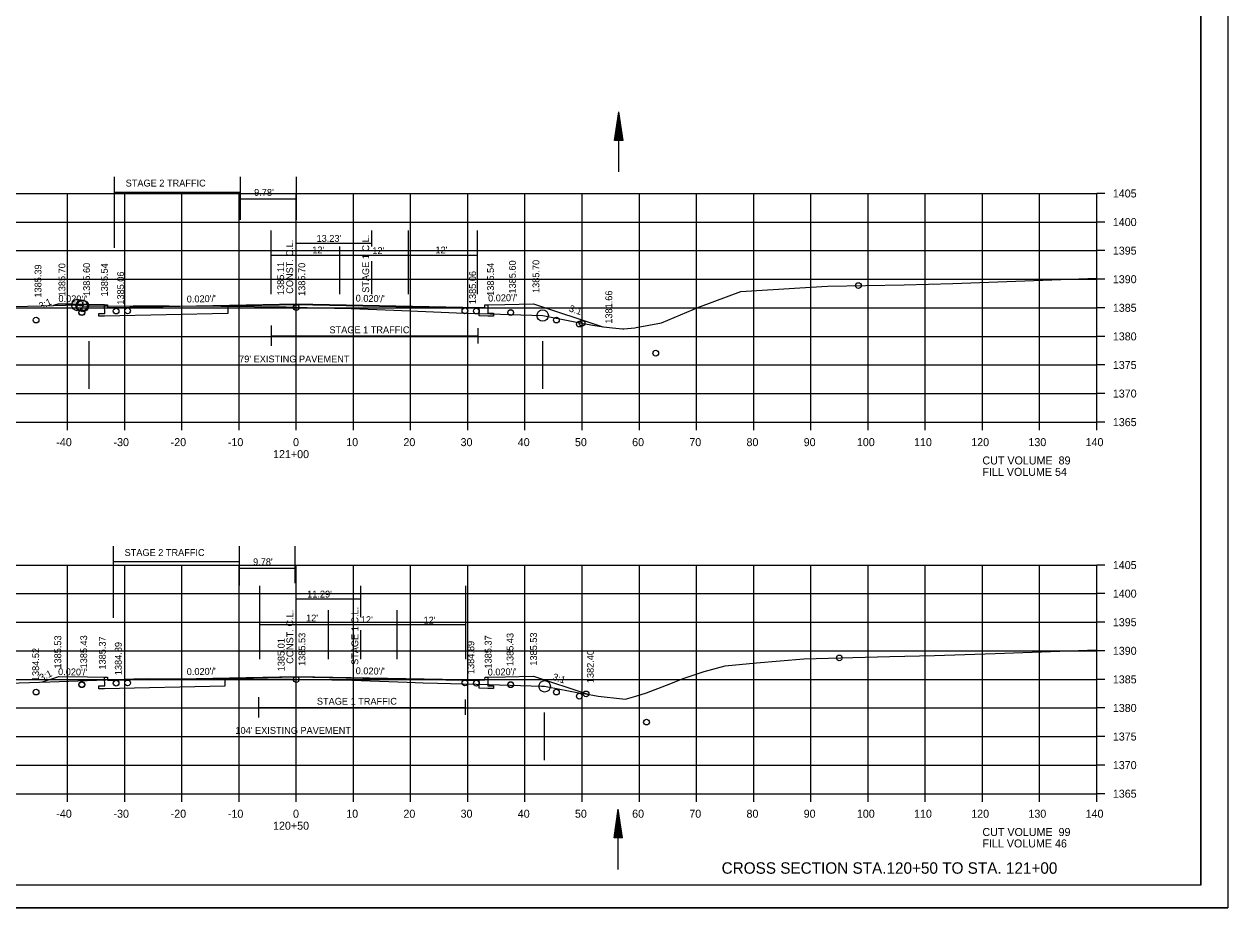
# Model space of a CAD drawing. Extents: x 1374311 to 1383814, y 384102 to 406278.
# Drawn here: x 1381581.1 to 1381791.6, y 385391.3 to 385545.9 of the extents above; entities that cross this region are included whole.
import ezdxf

# ---------------------------------------------------------------- set-up
doc = ezdxf.new("R2010")
doc.units = 0
for name, color, linetype in [('R_Axis', 7, 'Continuous'), ('R_Axis Annot', 7, 'Continuous'), ('R_Border', 7, 'Continuous'), ('R_Draft', 7, 'Continuous'), ('R_Exist Surface', 7, 'Continuous'), ('R_Fin Surface', 7, 'Continuous'), ('R_Grid', 7, 'Continuous'), ('R_No Plot', 7, 'Continuous'), ('R_Water', 7, 'Continuous'), ('R_Xsect Elev', 7, 'Continuous'), ('R_Xsect Slope', 7, 'Continuous')]:
    doc.layers.add(name, color=color, linetype=linetype)

msp = doc.modelspace()

# ---------------------------------------------------------------- linework, layer by layer
at = {"layer": 'R_Axis'}
for p, q in [((1381768.66, 385476.27), (1381768.66, 385516.27)), ((1381770.06, 385516.27), (1381768.66, 385516.27)), ((1381770.06, 385511.27), (1381768.66, 385511.27)), ((1381770.06, 385506.27), (1381768.66, 385506.27)), ((1381770.06, 385501.27), (1381768.66, 385501.27)), ((1381770.06, 385496.27), (1381768.66, 385496.27)), ((1381770.06, 385491.27), (1381768.66, 385491.27)), ((1381770.06, 385486.27), (1381768.66, 385486.27)), ((1381770.06, 385481.27), (1381768.66, 385481.27)), ((1381488.66, 385476.27), (1381768.66, 385476.27)), ((1381588.66, 385474.87), (1381588.66, 385476.27)), ((1381598.66, 385474.87), (1381598.66, 385476.27)), ((1381608.66, 385474.87), (1381608.66, 385476.27)), ((1381618.66, 385474.87), (1381618.66, 385476.27)), ((1381628.66, 385474.87), (1381628.66, 385476.27)), ((1381638.66, 385474.87), (1381638.66, 385476.27)), ((1381648.66, 385474.87), (1381648.66, 385476.27)), ((1381658.66, 385474.87), (1381658.66, 385476.27)), ((1381668.66, 385474.87), (1381668.66, 385476.27)), ((1381678.66, 385474.87), (1381678.66, 385476.27)), ((1381688.66, 385474.87), (1381688.66, 385476.27)), ((1381698.66, 385474.87), (1381698.66, 385476.27)), ((1381708.66, 385474.87), (1381708.66, 385476.27)), ((1381718.66, 385474.87), (1381718.66, 385476.27)), ((1381728.66, 385474.87), (1381728.66, 385476.27)), ((1381738.66, 385474.87), (1381738.66, 385476.27)), ((1381748.66, 385474.87), (1381748.66, 385476.27)), ((1381758.66, 385474.87), (1381758.66, 385476.27)), ((1381768.66, 385474.87), (1381768.66, 385476.27)), ((1381770.06, 385476.27), (1381768.66, 385476.27)), ((1381768.66, 385411.27), (1381768.66, 385451.27)), ((1381770.06, 385451.27), (1381768.66, 385451.27)), ((1381770.06, 385446.27), (1381768.66, 385446.27)), ((1381770.06, 385441.27), (1381768.66, 385441.27)), ((1381770.06, 385436.27), (1381768.66, 385436.27)), ((1381770.06, 385431.27), (1381768.66, 385431.27)), ((1381770.06, 385426.27), (1381768.66, 385426.27)), ((1381770.06, 385421.27), (1381768.66, 385421.27)), ((1381770.06, 385416.27), (1381768.66, 385416.27)), ((1381488.66, 385411.27), (1381768.66, 385411.27)), ((1381588.66, 385409.87), (1381588.66, 385411.27)), ((1381598.66, 385409.87), (1381598.66, 385411.27)), ((1381608.66, 385409.87), (1381608.66, 385411.27)), ((1381618.66, 385409.87), (1381618.66, 385411.27)), ((1381628.66, 385409.87), (1381628.66, 385411.27)), ((1381638.66, 385409.87), (1381638.66, 385411.27)), ((1381648.66, 385409.87), (1381648.66, 385411.27)), ((1381658.66, 385409.87), (1381658.66, 385411.27)), ((1381668.66, 385409.87), (1381668.66, 385411.27)), ((1381678.66, 385409.87), (1381678.66, 385411.27)), ((1381688.66, 385409.87), (1381688.66, 385411.27)), ((1381698.66, 385409.87), (1381698.66, 385411.27)), ((1381708.66, 385409.87), (1381708.66, 385411.27)), ((1381718.66, 385409.87), (1381718.66, 385411.27)), ((1381728.66, 385409.87), (1381728.66, 385411.27)), ((1381738.66, 385409.87), (1381738.66, 385411.27)), ((1381748.66, 385409.87), (1381748.66, 385411.27)), ((1381758.66, 385409.87), (1381758.66, 385411.27)), ((1381768.66, 385409.87), (1381768.66, 385411.27)), ((1381770.06, 385411.27), (1381768.66, 385411.27))]:
    msp.add_line(p, q, dxfattribs=at)
at = {"layer": 'R_Border'}
for q in [(1381786.84, 385600.73), (1381470.66, 385395.27)]:
    msp.add_line((1381786.84, 385395.27), q, dxfattribs=at)
at = {"layer": 'R_Draft'}
for p, q in [((1381684.33, 385525.56), (1381685.08, 385530.56)), ((1381684.46, 385525.56), (1381685.08, 385529.72)), ((1381684.59, 385525.56), (1381685.08, 385528.86)), ((1381685.83, 385525.56), (1381685.08, 385530.56)), ((1381685.71, 385525.56), (1381685.08, 385529.72)), ((1381685.58, 385525.56), (1381685.08, 385528.86)), ((1381684.71, 385525.56), (1381685.08, 385528.03)), ((1381684.84, 385525.56), (1381685.08, 385527.18)), ((1381685.46, 385525.56), (1381685.08, 385528.03)), ((1381685.33, 385525.56), (1381685.08, 385527.18)), ((1381685.83, 385525.56), (1381684.33, 385525.56)), ((1381684.97, 385525.56), (1381685.08, 385526.35)), ((1381685.2, 385525.56), (1381685.08, 385526.35)), ((1381684.23, 385403.55), (1381684.98, 385408.55)), ((1381684.36, 385403.55), (1381684.98, 385407.72)), ((1381684.49, 385403.55), (1381684.98, 385406.86)), ((1381685.73, 385403.55), (1381684.98, 385408.55)), ((1381685.61, 385403.55), (1381684.98, 385407.72)), ((1381685.48, 385403.55), (1381684.98, 385406.86)), ((1381684.61, 385403.55), (1381684.98, 385406.02)), ((1381684.74, 385403.55), (1381684.98, 385405.18)), ((1381685.36, 385403.55), (1381684.98, 385406.02)), ((1381685.23, 385403.55), (1381684.98, 385405.18)), ((1381685.73, 385403.55), (1381684.23, 385403.55)), ((1381684.87, 385403.55), (1381684.98, 385404.34)), ((1381685.1, 385403.55), (1381684.98, 385404.34))]:
    msp.add_line(p, q, dxfattribs=at)
at = {"layer": 'R_Exist Surface'}
for points in [[(1381566.63, 385496.21), (1381584.14, 385496.61), (1381590.37, 385496.77), (1381590.75, 385496.7), (1381591.14, 385496.66), (1381591.22, 385496.59), (1381591.35, 385496.58), (1381600.13, 385496.61), (1381602.79, 385496.61), (1381606.43, 385496.6), (1381615.47, 385496.58), (1381621.3, 385496.51), (1381626.89, 385496.43), (1381632.35, 385496.29), (1381638.29, 385496.15), (1381645.72, 385495.87), (1381651.3, 385495.65), (1381656.7, 385495.42), (1381662.59, 385495.19), (1381667.95, 385495.02), (1381671.76, 385494.91), (1381676.77, 385493.95), (1381678.18, 385493.66), (1381680.5, 385493.26), (1381682.39, 385492.92), (1381683.95, 385492.76), (1381685.73, 385492.59), (1381685.97, 385492.62), (1381687.85, 385492.76), (1381688.1, 385492.8), (1381692.56, 385493.62), (1381698.05, 385495.99), (1381698.99, 385496.39), (1381699.34, 385496.51), (1381706.38, 385499.12), (1381716.72, 385499.78), (1381721.58, 385500.07), (1381734.99, 385500.28), (1381743.49, 385500.53), (1381768.66, 385501.48)], [(1381573.05, 385430.41), (1381585.57, 385430.84), (1381600.25, 385431.34), (1381600.44, 385431.36), (1381602.76, 385431.4), (1381614.38, 385431.38), (1381614.97, 385431.38), (1381615.52, 385431.37), (1381626.91, 385431.31), (1381627.83, 385431.29), (1381638.38, 385431.14), (1381648.06, 385430.79), (1381650.88, 385430.69), (1381653.36, 385430.61), (1381662.38, 385430.36), (1381671.55, 385430.07), (1381672.1, 385430.06), (1381672.63, 385429.95), (1381678.06, 385428.93), (1381678.93, 385428.8), (1381681.43, 385428.36), (1381685.74, 385427.85), (1381686.31, 385427.78), (1381686.4, 385427.84), (1381688.06, 385428.36), (1381689.94, 385428.91), (1381693.38, 385430.25), (1381696.52, 385431.49), (1381699.98, 385432.64), (1381703.67, 385433.63), (1381709.14, 385434.16), (1381717.45, 385434.86), (1381732.46, 385435.27), (1381740.27, 385435.44), (1381750.89, 385435.82), (1381768.66, 385436.44)]]:
    msp.add_lwpolyline(points, dxfattribs=at)
at = {"layer": 'R_Fin Surface'}
for points in [[(1381586.23, 385496.67), (1381587.15, 385496.97), (1381592.15, 385496.87), (1381595.15, 385496.81), (1381595.65, 385496.81), (1381595.66, 385496.31), (1381596.66, 385496.33), (1381628.66, 385496.97), (1381628.66, 385496.97)], [(1381628.66, 385496.8), (1381628.66, 385496.8), (1381616.68, 385496.56), (1381616.68, 385495.25), (1381595.15, 385494.82), (1381594.15, 385494.8), (1381594.16, 385495.3), (1381595.16, 385495.3), (1381595.14, 385496.81)], [(1381628.66, 385496.97), (1381660.65, 385496.33)], [(1381660.65, 385496.16), (1381628.66, 385496.8)], [(1381660.65, 385496.33), (1381661.64, 385496.31), (1381661.65, 385496.81), (1381662.15, 385496.81), (1381665.15, 385496.87), (1381670.15, 385496.97), (1381682.26, 385492.94)], [(1381662.16, 385496.81), (1381662.17, 385495.31), (1381663.17, 385495.31), (1381663.16, 385494.81), (1381662.16, 385494.83), (1381660.65, 385494.85), (1381660.65, 385496.16)], [(1381584.12, 385430.79), (1381587.15, 385431.8), (1381592.15, 385431.7), (1381595.15, 385431.64), (1381595.65, 385431.64), (1381595.66, 385431.14), (1381596.66, 385431.16), (1381628.66, 385431.8), (1381660.66, 385431.19), (1381661.66, 385431.17), (1381661.67, 385431.67), (1381662.17, 385431.67), (1381665.17, 385431.73), (1381670.17, 385431.83), (1381679.66, 385428.67)], [(1381662.16, 385431.67), (1381662.18, 385430.16), (1381663.18, 385430.16), (1381663.17, 385429.66), (1381662.17, 385429.68), (1381660.66, 385429.71), (1381660.66, 385431.02), (1381628.66, 385431.63), (1381616.17, 385431.38), (1381616.17, 385430.06), (1381595.15, 385429.64), (1381594.15, 385429.62), (1381594.16, 385430.12), (1381595.16, 385430.13), (1381595.14, 385431.64)]]:
    msp.add_lwpolyline(points, dxfattribs=at)
at = {"layer": 'R_Grid'}
for p, q in [((1381488.66, 385516.27), (1381768.66, 385516.27)), ((1381588.66, 385476.27), (1381588.66, 385516.27)), ((1381598.66, 385476.27), (1381598.66, 385516.27)), ((1381608.66, 385476.27), (1381608.66, 385516.27)), ((1381618.66, 385476.27), (1381618.66, 385516.27)), ((1381628.66, 385476.27), (1381628.66, 385516.27)), ((1381638.66, 385476.27), (1381638.66, 385516.27)), ((1381648.66, 385476.27), (1381648.66, 385516.27)), ((1381658.66, 385476.27), (1381658.66, 385516.27)), ((1381668.66, 385476.27), (1381668.66, 385516.27)), ((1381678.66, 385476.27), (1381678.66, 385516.27)), ((1381688.66, 385476.27), (1381688.66, 385516.27)), ((1381698.66, 385476.27), (1381698.66, 385516.27)), ((1381708.66, 385476.27), (1381708.66, 385516.27)), ((1381718.66, 385476.27), (1381718.66, 385516.27)), ((1381728.66, 385476.27), (1381728.66, 385516.27)), ((1381738.66, 385476.27), (1381738.66, 385516.27)), ((1381748.66, 385476.27), (1381748.66, 385516.27)), ((1381758.66, 385476.27), (1381758.66, 385516.27)), ((1381768.66, 385476.27), (1381768.66, 385516.27)), ((1381488.66, 385511.27), (1381768.66, 385511.27)), ((1381488.66, 385506.27), (1381768.66, 385506.27)), ((1381488.66, 385501.27), (1381768.66, 385501.27)), ((1381488.66, 385496.27), (1381768.66, 385496.27)), ((1381488.66, 385491.27), (1381768.66, 385491.27)), ((1381488.66, 385486.27), (1381768.66, 385486.27)), ((1381488.66, 385481.27), (1381768.66, 385481.27)), ((1381488.66, 385476.27), (1381768.66, 385476.27)), ((1381488.66, 385451.27), (1381768.66, 385451.27)), ((1381588.66, 385411.27), (1381588.66, 385451.27)), ((1381598.66, 385411.27), (1381598.66, 385451.27)), ((1381608.66, 385411.27), (1381608.66, 385451.27)), ((1381618.66, 385411.27), (1381618.66, 385451.27)), ((1381628.66, 385411.27), (1381628.66, 385451.27)), ((1381638.66, 385411.27), (1381638.66, 385451.27)), ((1381648.66, 385411.27), (1381648.66, 385451.27)), ((1381658.66, 385411.27), (1381658.66, 385451.27)), ((1381668.66, 385411.27), (1381668.66, 385451.27)), ((1381678.66, 385411.27), (1381678.66, 385451.27)), ((1381688.66, 385411.27), (1381688.66, 385451.27)), ((1381698.66, 385411.27), (1381698.66, 385451.27)), ((1381708.66, 385411.27), (1381708.66, 385451.27)), ((1381718.66, 385411.27), (1381718.66, 385451.27)), ((1381728.66, 385411.27), (1381728.66, 385451.27)), ((1381738.66, 385411.27), (1381738.66, 385451.27)), ((1381748.66, 385411.27), (1381748.66, 385451.27)), ((1381758.66, 385411.27), (1381758.66, 385451.27)), ((1381768.66, 385411.27), (1381768.66, 385451.27)), ((1381488.66, 385446.27), (1381768.66, 385446.27)), ((1381488.66, 385441.27), (1381768.66, 385441.27)), ((1381488.66, 385436.27), (1381768.66, 385436.27)), ((1381488.66, 385431.27), (1381768.66, 385431.27)), ((1381488.66, 385426.27), (1381768.66, 385426.27)), ((1381488.66, 385421.27), (1381768.66, 385421.27)), ((1381488.66, 385416.27), (1381768.66, 385416.27)), ((1381488.66, 385411.27), (1381768.66, 385411.27))]:
    msp.add_line(p, q, dxfattribs=at)
at = {"layer": 'R_No Plot'}
msp.add_line((1381458.26, 385391.29), (1381791.59, 385391.29), dxfattribs=at)
for points in [[(1381458.25, 385604.63), (1381791.59, 385604.63), (1381791.59, 385391.29), (1381458.25, 385391.29)], [(1381704.58, 385600.73), (1381704.58, 385590.85), (1381740.31, 385590.85), (1381740.31, 385587.93), (1381763.51, 385587.93), (1381763.51, 385564.72), (1381786.84, 385564.72), (1381786.84, 385395.27), (1381470.66, 385395.27), (1381470.66, 385600.73)], [(1381586.23, 385496.67), (1381590.37, 385496.77), (1381590.75, 385496.7), (1381591.14, 385496.66), (1381591.22, 385496.59), (1381591.35, 385496.58), (1381595.15, 385496.59), (1381595.15, 385496.81), (1381592.15, 385496.87), (1381587.15, 385496.97)]]:
    msp.add_lwpolyline(points, close=True, dxfattribs=at)
for centre, radius in [((1381726.97, 385500.15), 0.5), ((1381590.37, 385496.77), 1), ((1381591.14, 385496.66), 1), ((1381591.35, 385496.58), 1), ((1381591.16, 385495.46), 0.5), ((1381591.16, 385495.42), 0.5), ((1381597.16, 385495.7), 0.5), ((1381599.16, 385495.74), 0.5), ((1381599.16, 385495.74), 0.5), ((1381628.66, 385496.33), 0.5), ((1381628.66, 385496.33), 0.5), ((1381658.16, 385495.74), 0.5), ((1381658.16, 385495.74), 0.5), ((1381660.16, 385495.7), 0.5), ((1381666.16, 385495.46), 0.5), ((1381666.16, 385495.42), 0.5), ((1381671.76, 385494.91), 1), ((1381583.16, 385494.13), 0.5), ((1381674.16, 385494.13), 0.5), ((1381678.16, 385493.42), 0.5), ((1381678.64, 385493.58), 0.5), ((1381691.53, 385488.34), 0.5), ((1381723.63, 385435.03), 0.5), ((1381591.16, 385430.37), 0.5), ((1381591.16, 385430.33), 0.5), ((1381597.16, 385430.61), 0.5), ((1381599.16, 385430.65), 0.5), ((1381599.16, 385430.65), 0.5), ((1381628.66, 385431.24), 0.5), ((1381628.66, 385431.24), 0.5), ((1381658.16, 385430.65), 0.5), ((1381658.16, 385430.65), 0.5), ((1381660.16, 385430.61), 0.5), ((1381666.16, 385430.37), 0.5), ((1381666.16, 385430.33), 0.5), ((1381672.1, 385430.06), 1), ((1381583.16, 385429.04), 0.5), ((1381674.16, 385429.04), 0.5), ((1381678.16, 385428.33), 0.5), ((1381679.34, 385428.73), 0.5), ((1381689.91, 385423.79), 0.5)]:
    msp.add_circle(centre, radius, dxfattribs=at)
at = {"layer": 'R_Water'}
for p, q in [((1381685.08, 385520.05), (1381685.08, 385530.56)), ((1381596.9, 385506.74), (1381596.9, 385519.18)), ((1381618.9, 385511.66), (1381618.9, 385519.18)), ((1381628.68, 385511.66), (1381628.68, 385519.18)), ((1381596.9, 385516.52), (1381618.9, 385516.52)), ((1381618.9, 385515.33), (1381628.68, 385515.33)), ((1381624.29, 385498.67), (1381624.29, 385509.81)), ((1381628.66, 385506.97), (1381628.66, 385509.81)), ((1381641.89, 385506.97), (1381641.89, 385509.81)), ((1381648.31, 385498.67), (1381648.31, 385509.81)), ((1381660.36, 385498.67), (1381660.36, 385509.81)), ((1381628.66, 385507.58), (1381641.89, 385507.58)), ((1381636.29, 385498.67), (1381636.29, 385506.97)), ((1381624.29, 385505.5), (1381660.36, 385505.5)), ((1381628.66, 385498.67), (1381628.66, 385504.34)), ((1381641.89, 385498.67), (1381641.89, 385504.42)), ((1381628.66, 385496.97), (1381660.65, 385496.33)), ((1381624.34, 385489.61), (1381624.34, 385493.16)), ((1381624.33, 385491.37), (1381660.47, 385491.37)), ((1381660.47, 385490.02), (1381660.47, 385492.71)), ((1381592.43, 385482.12), (1381592.43, 385490.45)), ((1381671.76, 385482.12), (1381671.76, 385490.45)), ((1381592.43, 385486.29), (1381671.76, 385486.29)), ((1381596.71, 385442.05), (1381596.71, 385454.55)), ((1381618.71, 385447.72), (1381618.71, 385454.55)), ((1381628.49, 385448.08), (1381628.49, 385454.55)), ((1381596.71, 385451.89), (1381618.71, 385451.89)), ((1381618.71, 385450.7), (1381628.49, 385450.7)), ((1381622.32, 385434.8), (1381622.32, 385447.64)), ((1381628.65, 385443.39), (1381628.65, 385447.53)), ((1381639.95, 385442.17), (1381639.95, 385447.64)), ((1381658.32, 385434.8), (1381658.32, 385447.64)), ((1381628.7, 385445.35), (1381639.95, 385445.35)), ((1381634.32, 385434.8), (1381634.32, 385443.39)), ((1381646.32, 385434.8), (1381646.32, 385443.39)), ((1381622.41, 385440.86), (1381658.32, 385440.86)), ((1381628.65, 385434.69), (1381628.65, 385440.59)), ((1381639.95, 385434.8), (1381639.95, 385439.86)), ((1381622.14, 385424.63), (1381622.14, 385428.18)), ((1381658.27, 385425.04), (1381658.27, 385427.73)), ((1381622.13, 385426.38), (1381658.27, 385426.38)), ((1381672.1, 385417.14), (1381672.1, 385425.46)), ((1381568.22, 385421.3), (1381672.1, 385421.3)), ((1381684.98, 385398.04), (1381684.98, 385408.55))]:
    msp.add_line(p, q, dxfattribs=at)

# ---------------------------------------------------------------- texts
at = {"layer": 'R_Axis Annot'}
for s, p in [('1405', (1381771.46, 385515.57)), ('1400', (1381771.46, 385510.57)), ('1395', (1381771.46, 385505.57)), ('1390', (1381771.46, 385500.57)), ('1385', (1381771.46, 385495.57)), ('1380', (1381771.46, 385490.57)), ('1375', (1381771.46, 385485.57)), ('1370', (1381771.46, 385480.57)), ('1365', (1381771.46, 385475.57)), ('-40', (1381586.7, 385472.07)), ('-30', (1381596.7, 385472.07)), ('-20', (1381606.7, 385472.07)), ('-10', (1381616.7, 385472.07)), ('0', (1381628.1, 385472.07)), ('10', (1381637.4, 385472.07)), ('20', (1381647.4, 385472.07)), ('30', (1381657.4, 385472.07)), ('40', (1381667.4, 385472.07)), ('50', (1381677.4, 385472.07)), ('60', (1381687.4, 385472.07)), ('70', (1381697.4, 385472.07)), ('80', (1381707.4, 385472.07)), ('90', (1381717.4, 385472.07)), ('100', (1381726.7, 385472.07)), ('110', (1381736.7, 385472.07)), ('120', (1381746.7, 385472.07)), ('130', (1381756.7, 385472.07)), ('140', (1381766.7, 385472.07)), ('121+00', (1381624.6, 385469.97)), ('CUT VOLUME  89', (1381748.66, 385468.87)), ('FILL VOLUME 54', (1381748.66, 385466.87)), ('1405', (1381771.46, 385450.57)), ('1400', (1381771.46, 385445.57)), ('1395', (1381771.46, 385440.57)), ('1390', (1381771.46, 385435.57)), ('1385', (1381771.46, 385430.57)), ('1380', (1381771.46, 385425.57)), ('1375', (1381771.46, 385420.57)), ('1370', (1381771.46, 385415.57)), ('1365', (1381771.46, 385410.57)), ('-40', (1381586.7, 385407.07)), ('-30', (1381596.7, 385407.07)), ('-20', (1381606.7, 385407.07)), ('-10', (1381616.7, 385407.07)), ('0', (1381628.1, 385407.07)), ('10', (1381637.4, 385407.07)), ('20', (1381647.4, 385407.07)), ('30', (1381657.4, 385407.07)), ('40', (1381667.4, 385407.07)), ('50', (1381677.4, 385407.07)), ('60', (1381687.4, 385407.07)), ('70', (1381697.4, 385407.07)), ('80', (1381707.4, 385407.07)), ('90', (1381717.4, 385407.07)), ('100', (1381726.7, 385407.07)), ('110', (1381736.7, 385407.07)), ('120', (1381746.7, 385407.07)), ('130', (1381756.7, 385407.07)), ('140', (1381766.7, 385407.07)), ('120+50', (1381624.6, 385404.97)), ('CUT VOLUME  99', (1381748.66, 385403.87)), ('FILL VOLUME 46', (1381748.66, 385401.87))]:
    msp.add_text(s, height=1.4, dxfattribs=at).set_placement(p)
at = {"layer": 'R_Draft'}
msp.add_text('CROSS SECTION STA.120+50 TO STA. 121+00', height=2, dxfattribs=at).set_placement((1381703.05, 385397.27))
at = {"layer": 'R_Water'}
for s, p in [('STAGE 2 TRAFFIC', (1381598.83, 385517.49)), ("9.78'", (1381621.3, 385515.86)), ("13.23'", (1381632.21, 385507.81)), ("12'", (1381631.46, 385505.79)), ("12'", (1381641.97, 385505.67)), ("12'", (1381653, 385505.78)), ('STAGE 1 TRAFFIC', (1381634.47, 385491.82)), ("79' EXISTING PAVEMENT", (1381618.67, 385486.72)), ('STAGE 2 TRAFFIC', (1381598.64, 385452.86)), ("9.78'", (1381621.11, 385451.23)), ("11.29'", (1381630.57, 385445.59)), ("12'", (1381630.38, 385441.4)), ("12'", (1381639.96, 385441.12)), ("12'", (1381650.92, 385441.03)), ('STAGE 1 TRAFFIC', (1381632.27, 385426.84)), ("104' EXISTING PAVEMENT", (1381618.03, 385421.74))]:
    msp.add_text(s, height=1.2, dxfattribs=at).set_placement(p)
for s, p in [('CONST. C.L.', (1381628.12, 385498.73)), ('STAGE 1 C.L.', (1381641.41, 385498.89)), ('CONST. C.L.', (1381628.15, 385434)), ('STAGE 1 C.L.', (1381639.51, 385433.8))]:
    msp.add_text(s, height=1.2, rotation=90, dxfattribs=at).set_placement(p)
at = {"layer": 'R_Xsect Elev'}
for s, p in [('1385.39', (1381584.1, 385498.06)), ('1385.70', (1381588.29, 385498.28)), ('1385.60', (1381592.6, 385498.34)), ('1385.54', (1381595.72, 385498.26)), ('1385.11', (1381626.54, 385498.5)), ('1385.70', (1381630.23, 385498.35)), ('1385.54', (1381663.24, 385498.36)), ('1385.60', (1381667.06, 385498.77)), ('1385.70', (1381671.18, 385498.86)), ('1385.06', (1381598.55, 385496.82)), ('1385.06', (1381660.09, 385496.91)), ('1381.66', (1381683.92, 385493.49)), ('1385.53', (1381587.56, 385433.16)), ('1385.43', (1381592.09, 385433.19)), ('1385.37', (1381595.35, 385432.99)), ('1385.01', (1381626.62, 385432.68)), ('1385.53', (1381630.26, 385433.62)), ('1385.37', (1381662.83, 385433.17)), ('1385.43', (1381666.65, 385433.59)), ('1385.53', (1381670.76, 385433.67)), ('1384.52', (1381583.69, 385430.97)), ('1384.89', (1381598.14, 385432.01)), ('1384.89', (1381659.79, 385432.2)), ('1382.40', (1381680.69, 385430.61))]:
    msp.add_text(s, height=1.2, rotation=90, dxfattribs=at).set_placement(p)
at = {"layer": 'R_Xsect Slope'}
for s, rotation, p in [('3:1', 25.1363, (1381583.99, 385495.97)), ("0.020'/'", 358.8542, (1381587.06, 385497.3)), ("0.020'/'", 1.1458, (1381609.52, 385497.19)), ("0.020'/'", 358.8542, (1381639.04, 385497.36)), ("0.020'/'", 1.1458, (1381662.22, 385497.36)), ('3:1', 341.5651, (1381676.26, 385495.67)), ('3:1', 25.1363, (1381584.07, 385430.95)), ("0.020'/'", 358.8542, (1381587, 385432.03)), ("0.020'/'", 1.1458, (1381609.52, 385432.01)), ("0.020'/'", 358.8542, (1381639.04, 385432.19)), ("0.020'/'", 1.1458, (1381662.15, 385431.93)), ('3:1', 341.5651, (1381673.39, 385431.23))]:
    msp.add_text(s, height=1.2, rotation=rotation, dxfattribs=at).set_placement(p)

doc.saveas('drawing.dxf')
